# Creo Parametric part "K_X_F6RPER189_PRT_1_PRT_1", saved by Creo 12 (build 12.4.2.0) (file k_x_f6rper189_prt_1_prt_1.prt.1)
Units: Custom; MM, KILOGRAM, SECS

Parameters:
  PTC_WM_ITERATION = "0"
  PTC_WM_VERSION = "-.0"
  PTC_WM_LIFECYCLE_STATE = "In Work"
  PTC_WM_LIFECYCLE = "MO_CADDocument"
  PTC_WM_CREATED_BY = "Maximilian Roepper (Z0017RMS: MO)"
  PTC_WM_CREATED_ON = "18-Sep-26 11:36:42 AM"
  PTC_WM_MODIFIED_BY = "Maximilian Roepper (Z0017RMS: MO)"
  PTC_WM_MODIFIED_ON = "18-Sep-26 11:36:46 AM"
  PDMLINKNUMBER = "PDM000071455102"
  PTC_WM_NAME = "k_x_f6rper189_prt_1_prt_1.prt"
  PTC_WM_NUMBER = "PDM000071455102"

Other parameters: WEIGHT, WEIGHT_FACTOR, WEIGHT_ADD, _MASS_TEMP, _DIFF_TEMP, MC_ERRORS, SUPPLIER

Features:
  1. coordinate system
  2. datum plane "PRT_YZ"
  3. datum plane "PRT_XY"
  4. datum plane "PRT_XZ"
  5. coordinate system
  6. datum axis
  7. datum axis
  8. datum axis
  9. coordinate system
  10. imported feature
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
Other named items: PRT, SIEMENS_MO, DRW_VIEW_ORG, PRT_X, PRT_Y, PRT_Z, CS0, ROUGH_GROB

Layers: 00_STD_CSYS-KSYS, 01_STD_PLANES-EBENEN, 02_STD_AXES-ACHSEN, 03_STD_CSYS-KSYS, 24_IMPORT_FEAT-IMPORT_KE

Surfaces: 15 plane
